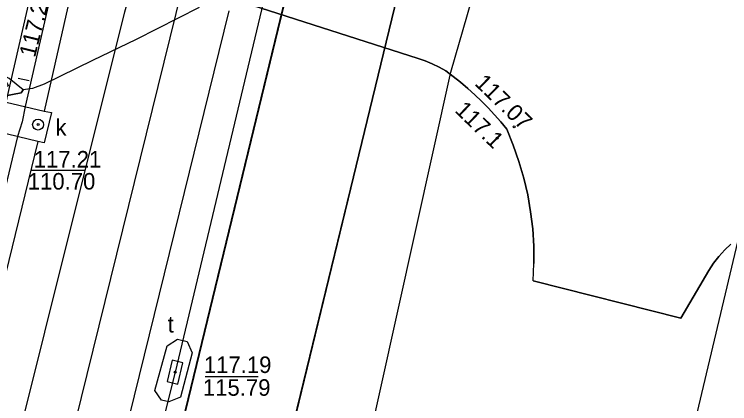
# Model space of a CAD drawing. Extents: x 6424617 to 6425697, y 5665845 to 5667190.
# Drawn here: x 6425396.34 to 6425428.81, y 5666458.45 to 5666476.12 of the extents above; entities that cross this region are included whole.
import ezdxf

# ---------------------------------------------------------------- set-up
doc = ezdxf.new("R2010")
doc.units = 0
for name, color, linetype in [('Warstwa 1', 7, 'Continuous'), ('Warstwa 10', 7, 'Continuous'), ('Warstwa 12', 7, 'Continuous'), ('Warstwa 13', 7, 'Continuous'), ('Warstwa 14', 7, 'Continuous'), ('Warstwa 15', 7, 'Continuous'), ('Warstwa 16', 7, 'Continuous'), ('Warstwa 25', 7, 'Continuous'), ('Warstwa 4', 7, 'Continuous'), ('Warstwa 5', 7, 'Continuous'), ('Warstwa 6', 7, 'Continuous'), ('Warstwa 61', 7, 'Continuous'), ('Warstwa 8', 7, 'Continuous')]:
    doc.layers.add(name, color=color, linetype=linetype)

msp = doc.modelspace()

# ---------------------------------------------------------------- linework, layer by layer
at = {"layer": 'Warstwa 1'}
for p, q in [((6425386.659, 5666386.227), (6425410.054, 5666482.642)), ((6425386.659, 5666386.227), (6425410.054, 5666482.642)), ((6425403.054, 5666432.953), (6425414.841, 5666481.544)), ((6425403.054, 5666432.953), (6425414.841, 5666481.544))]:
    msp.add_line(p, q, dxfattribs=at)
at = {"layer": 'Warstwa 10'}
msp.add_lwpolyline([(6425366.705, 5666313.952), (6425374.377, 5666346.412), (6425379.54, 5666367.762), (6425384.145, 5666386.807), (6425386.47, 5666396.26), (6425387.262, 5666397.301), (6425387.592, 5666398.097), (6425387.733, 5666398.995), (6425387.709, 5666399.495), (6425387.343, 5666399.88), (6425386.965, 5666400.004), (6425386.594, 5666399.939), (6425386.058, 5666399.445), (6425385.73, 5666398.749), (6425385.842, 5666398.098), (6425386.29, 5666397.932), (6425386.995, 5666398.354), (6425396.389, 5666436.784), (6425406.092, 5666476.274)], dxfattribs=at)
at = {"layer": 'Warstwa 12'}
for points in [[(6425424.798, 5666563.269), (6425407.429, 5666491.384), (6425382.182, 5666389.031), (6425381.68, 5666386.39)], [(6425428.997, 5666563.219), (6425416.238, 5666512.78), (6425403.639, 5666459.878), (6425390.212, 5666406.396)], [(6425380.898, 5666313.781), (6425400.051, 5666402.067), (6425408.909, 5666440.823), (6425416.154, 5666473.488), (6425420.109, 5666487.161), (6425420.685, 5666489.264), (6425421.019, 5666490.41), (6425433.788, 5666544.17), (6425438.345, 5666557.965), (6425447.158, 5666555.689), (6425449.696, 5666562.969)], [(6425407.795, 5666377.502), (6425413.082, 5666398.74), (6425423.493, 5666441.827), (6425434.167, 5666486.832), (6425447.141, 5666536.008)], [(6425395.979, 5666472.131), (6425406.757, 5666519.155)], [(6425408.386, 5666518.801), (6425397.699, 5666471.725)], [(6425363.057, 5666313.996), (6425363.589, 5666315.638), (6425368.024, 5666336.247), (6425374.227, 5666364.401), (6425379.433, 5666385.463), (6425383.671, 5666403.831), (6425384.666, 5666408.47), (6425384.841, 5666409.038), (6425384.956, 5666409.631), (6425387.736, 5666421.374), (6425394.087, 5666447.16), (6425401.357, 5666476.231), (6425405.643, 5666491.609), (6425405.786, 5666494.624), (6425411.34, 5666514.966), (6425411.306, 5666515.732)], [(6425404.728, 5666476.426), (6425401.871, 5666474.97), (6425399.899, 5666474.024), (6425397.696, 5666472.94), (6425397.164, 5666472.757), (6425396.753, 5666472.692)], [(6425396.753, 5666472.692), (6425396.117, 5666473.2), (6425395.791, 5666473.373), (6425396.075, 5666472.87), (6425395.302, 5666472.609), (6425394.886, 5666472.114), (6425394.383, 5666470.27), (6425391.685, 5666465.432), (6425388.484, 5666453.78)], [(6425366.353, 5666362.72), (6425369.879, 5666376.399), (6425373.51, 5666391.396), (6425377.162, 5666406.423), (6425378.544, 5666412.437), (6425386.549, 5666444.283), (6425388.297, 5666450.692), (6425392.281, 5666465.105), (6425394.427, 5666468.919), (6425394.601, 5666469.247), (6425394.673, 5666469.407), (6425394.808, 5666469.795), (6425394.976, 5666470.533), (6425395.345, 5666472.079), (6425395.789, 5666472.383), (6425396.66, 5666472.55), (6425396.753, 5666472.692)], [(6425397.417, 5666470.35), (6425385.979, 5666423.481)]]:
    msp.add_lwpolyline(points, dxfattribs=at)
at = {"layer": 'Warstwa 13'}
msp.add_circle((6425418.254, 5666470.495), 0.045, dxfattribs=at)
at = {"layer": 'Warstwa 14'}
for p, q in [((6425397.145, 5666469.04), (6425399.557, 5666469.04)), ((6425405.01, 5666459.682), (6425407.412, 5666459.682))]:
    msp.add_line(p, q, dxfattribs=at)
for centre in [(6425397.424, 5666471.114), (6425403.639, 5666459.878)]:
    msp.add_circle(centre, 0.045, dxfattribs=at)
at = {"layer": 'Warstwa 16'}
for points in [[(6425398.03, 5666471.666), (6425397.694, 5666470.28), (6425397.417, 5666470.35), (6425395.575, 5666470.784), (6425395.41, 5666470.808), (6425395.666, 5666472.185), (6425395.979, 5666472.131), (6425397.699, 5666471.725), (6425398.03, 5666471.666)], [(6425403.283, 5666461.072), (6425403.757, 5666461.377), (6425404.196, 5666461.271), (6425404.419, 5666460.759), (6425403.885, 5666458.745), (6425403.352, 5666458.531), (6425403.023, 5666458.615), (6425402.729, 5666459.049)]]:
    msp.add_lwpolyline(points, close=True, dxfattribs=at)
at = {"layer": 'Warstwa 25'}
msp.add_circle((6425419.029, 5666471.009), 0.045, dxfattribs=at)
at = {"layer": 'Warstwa 4'}
msp.add_lwpolyline([(6425396.525, 5666473.217), (6425397.014, 5666473.113)], dxfattribs=at)
msp.add_lwpolyline([(6425403.512, 5666460.422), (6425403.279, 5666459.45), (6425403.766, 5666459.334), (6425403.999, 5666460.306)], close=True, dxfattribs=at)
msp.add_circle((6425397.424, 5666471.114), 0.25, dxfattribs=at)
at = {"layer": 'Warstwa 6'}
for points in [[(6425386.659, 5666386.227), (6425410.054, 5666482.642), (6425433.754, 5666580.312), (6425463.303, 5666702.097), (6425474.6, 5666748.65), (6425473.47, 5666747.98), (6425465.93, 5666741.65), (6425451.88, 5666727.39), (6425441.06, 5666708.4), (6425429.67, 5666678.16), (6425407.73, 5666588.9), (6425390.68, 5666508.89), (6425364.93, 5666402.71), (6425352.06, 5666353.98)], [(6425491.527, 5666566.626), (6425489.08, 5666567.113), (6425471.272, 5666493.575), (6425449.122, 5666487.121), (6425445.943, 5666473.999), (6425426.498, 5666478.714), (6425414.841, 5666481.544), (6425403.054, 5666432.953), (6425420.811, 5666404.417), (6425453.223, 5666395.781)], [(6425428.868, 5666465.692), (6425428.585, 5666465.422), (6425428.322, 5666465.131), (6425428.081, 5666464.822), (6425427.864, 5666464.496), (6425426.596, 5666462.321), (6425419.892, 5666464.028), (6425419.927, 5666464.81), (6425419.92, 5666465.594), (6425419.869, 5666466.375), (6425419.777, 5666467.153), (6425419.642, 5666467.925), (6425419.465, 5666468.688), (6425419.247, 5666469.44), (6425418.988, 5666470.18), (6425418.69, 5666470.904), (6425418.418, 5666471.234), (6425418.137, 5666471.556), (6425417.847, 5666471.869), (6425417.547, 5666472.173), (6425417.239, 5666472.469), (6425416.923, 5666472.755), (6425416.598, 5666473.032), (6425416.265, 5666473.3), (6425415.924, 5666473.557), (6425415.621, 5666473.721), (6425415.31, 5666473.868), (6425414.991, 5666474), (6425414.666, 5666474.114), (6425406.328, 5666476.81)]]:
    msp.add_lwpolyline(points, dxfattribs=at)
msp.add_lwpolyline([(6425403.054, 5666432.953), (6425414.841, 5666481.544), (6425412.836, 5666481.999), (6425410.054, 5666482.642), (6425386.659, 5666386.227), (6425389.561, 5666385.562), (6425391.446, 5666385.129)], close=True, dxfattribs=at)
at = {"layer": 'Warstwa 61'}
msp.add_lwpolyline([(6425418.903, 5666563.341), (6425418.852, 5666563.142), (6425407.93, 5666520.767), (6425407.753, 5666519.862), (6425407.572, 5666518.978), (6425396.839, 5666471.928), (6425396.703, 5666471.243), (6425396.496, 5666470.567), (6425385.286, 5666423.635), (6425385.173, 5666423.021)], dxfattribs=at)
at = {"layer": 'Warstwa 8'}
for p, q in [((6425406.328, 5666476.81), (6425414.666, 5666474.114)), ((6425414.666, 5666474.114), (6425414.991, 5666474)), ((6425414.991, 5666474), (6425415.31, 5666473.868)), ((6425415.31, 5666473.868), (6425415.621, 5666473.721)), ((6425415.621, 5666473.721), (6425415.924, 5666473.557)), ((6425415.924, 5666473.557), (6425416.265, 5666473.3)), ((6425416.265, 5666473.3), (6425416.598, 5666473.032)), ((6425416.598, 5666473.032), (6425416.923, 5666472.755)), ((6425416.923, 5666472.755), (6425417.239, 5666472.469)), ((6425417.239, 5666472.469), (6425417.547, 5666472.173)), ((6425417.547, 5666472.173), (6425417.847, 5666471.869)), ((6425417.847, 5666471.869), (6425418.137, 5666471.556)), ((6425418.137, 5666471.556), (6425418.418, 5666471.234)), ((6425418.418, 5666471.234), (6425418.69, 5666470.904)), ((6425418.69, 5666470.904), (6425418.988, 5666470.18)), ((6425418.988, 5666470.18), (6425419.247, 5666469.44)), ((6425419.247, 5666469.44), (6425419.465, 5666468.688)), ((6425419.465, 5666468.688), (6425419.642, 5666467.925)), ((6425419.642, 5666467.925), (6425419.777, 5666467.153)), ((6425419.777, 5666467.153), (6425419.869, 5666466.375)), ((6425419.869, 5666466.375), (6425419.92, 5666465.594)), ((6425428.585, 5666465.422), (6425428.868, 5666465.692)), ((6425419.92, 5666465.594), (6425419.927, 5666464.81)), ((6425428.322, 5666465.131), (6425428.585, 5666465.422)), ((6425428.081, 5666464.822), (6425428.322, 5666465.131)), ((6425419.892, 5666464.028), (6425419.927, 5666464.81)), ((6425427.864, 5666464.496), (6425428.081, 5666464.822)), ((6425426.596, 5666462.321), (6425427.864, 5666464.496)), ((6425419.892, 5666464.028), (6425426.596, 5666462.321))]:
    msp.add_line(p, q, dxfattribs=at)
msp.add_lwpolyline([(6425404.728, 5666476.426), (6425401.871, 5666474.97), (6425399.899, 5666474.024), (6425397.696, 5666472.94), (6425397.164, 5666472.757), (6425396.753, 5666472.692), (6425396.66, 5666472.55), (6425395.789, 5666472.383)], dxfattribs=at)

# ---------------------------------------------------------------- texts
at = {"layer": 'Warstwa 13'}
msp.add_text('117.1', height=0.75, rotation=315.8602, dxfattribs=at).set_placement((6425416.296, 5666471.715))
at = {"layer": 'Warstwa 14'}
for s, p in [('110.70', (6425396.954, 5666468.165)), ('115.79', (6425404.903, 5666458.807))]:
    msp.add_text(s, height=0.75, dxfattribs=at).set_placement(p)
at = {"layer": 'Warstwa 15'}
for s, p in [('117.21', (6425397.224, 5666469.165)), ('117.19', (6425404.945, 5666459.84))]:
    msp.add_text(s, height=0.75, dxfattribs=at).set_placement(p)
at = {"layer": 'Warstwa 25'}
for s, rotation, p in [('117.20', 76.0487, (6425397.283, 5666474.126)), ('117.07', 315.8602, (6425417.195, 5666472.943))]:
    msp.add_text(s, height=0.75, rotation=rotation, dxfattribs=at).set_placement(p)
at = {"layer": 'Warstwa 5'}
for s, p in [('k', (6425398.213, 5666470.611)), ('t', (6425403.305, 5666461.677))]:
    msp.add_text(s, height=0.75, dxfattribs=at).set_placement(p)

doc.saveas('drawing.dxf')
